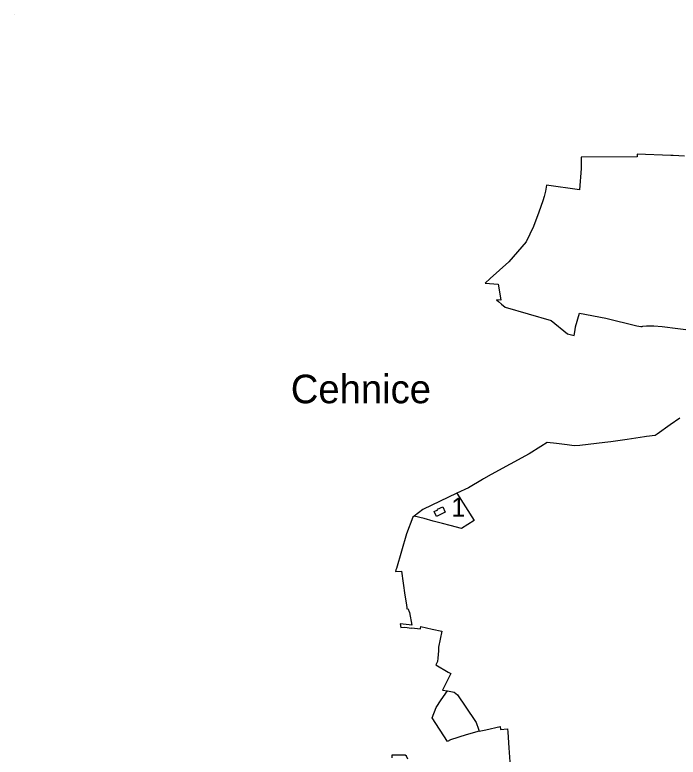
# Model space of a CAD drawing. Extents: x -783999 to -781353, y -1138035 to -1135203.
# Drawn here: x -783999 to -782885, y -1136634 to -1135387 of the extents above; entities that cross this region are included whole.
import ezdxf

# ---------------------------------------------------------------- set-up
doc = ezdxf.new("R2010")
doc.units = 0
for name, color, linetype in [('KU_OST', 7, 'Continuous'), ('LES_ZV', 7, 'Continuous'), ('Level 255', 7, 'Continuous'), ('NERES_HRA', 7, 'Continuous'), ('NERES_SET', 7, 'Continuous'), ('OVNE_PRE', 7, 'Continuous'), ('OVNI_SET', 7, 'Continuous')]:
    doc.layers.add(name, color=color, linetype=linetype)

msp = doc.modelspace()

# ---------------------------------------------------------------- linework, layer by layer
at = {"layer": 'LES_ZV'}
msp.add_lwpolyline([(-783220, -1136587.1), (-783219.2, -1136590.7), (-783241, -1136596.4), (-783267.4, -1136605.1), (-783272.2, -1136608), (-783297.9, -1136567.9), (-783291.4, -1136550.8), (-783282.6, -1136537.8), (-783272, -1136522.7)], dxfattribs=at)
at = {"layer": 'NERES_HRA'}
msp.add_lwpolyline([(-783294.3, -1136221.4), (-783288.3, -1136218.6), (-783288.7, -1136217.7), (-783280.2, -1136213.7), (-783275.9, -1136222.8), (-783290.5, -1136229.6), (-783294.3, -1136221.4)], dxfattribs=at)
at = {"layer": 'NERES_SET'}
msp.add_lwpolyline([(-783256.4, -1136190.8), (-783227.4, -1136236.5), (-783248.9, -1136250.2), (-783267.9, -1136245), (-783280.8, -1136241.5), (-783296, -1136237.4), (-783311.2, -1136233.2), (-783328, -1136229.2)], dxfattribs=at)
at = {"layer": 'OVNE_PRE'}
msp.add_line((-783998.9, -1135387.1), (-783998.9, -1135387.1), dxfattribs=at)
for points in [[(-782874.2, -1135624.5), (-782892.9, -1135623.6), (-782897.2, -1135623.4), (-782953.5, -1135620.9), (-782953.7, -1135625.5), (-783047.5, -1135626.2), (-783047.6, -1135645.2), (-783050.3, -1135680.9), (-783106.1, -1135673.1), (-783107.5, -1135683.3), (-783109.7, -1135692.3), (-783112.3, -1135699.7), (-783119, -1135718.4), (-783127.9, -1135742.9), (-783140.2, -1135768.7), (-783169.1, -1135801.8), (-783200.3, -1135830.3), (-783208.9, -1135838), (-783186.9, -1135839.7), (-783186.5, -1135842.2), (-783182.7, -1135866.6), (-783190, -1135865.9), (-783186.5, -1135868.9), (-783181.3, -1135873.3), (-783175.2, -1135878.4), (-783098.2, -1135900.8), (-783070.7, -1135923), (-783059.4, -1135925.7), (-783058, -1135916), (-783057.3, -1135911), (-783050.3, -1135888.2), (-783006.5, -1135896.5), (-782954, -1135909.4), (-782947.4, -1135910.7), (-782945.3, -1135910.4), (-782943.8, -1135910.2), (-782937.8, -1135909.3), (-782933, -1135909.4), (-782925.7, -1135909.8), (-782911.6, -1135910.4), (-782885.1, -1135913.8), (-782819.5, -1135922.3)], [(-782882, -1136064.9), (-782898.1, -1136076.1), (-782920, -1136091.3), (-782923.3, -1136093.5), (-782938, -1136095.7), (-782941.1, -1136096.1), (-782970.6, -1136100.4), (-782998.1, -1136104.3), (-783008, -1136105.7), (-783050, -1136110.5), (-783059.4, -1136111), (-783071.4, -1136109.6), (-783089.1, -1136107.4), (-783104.7, -1136105.5), (-783115.6, -1136112.3), (-783135, -1136124.4), (-783198.9, -1136159.1), (-783211.5, -1136166.6), (-783213.6, -1136167.8), (-783236.7, -1136181.5), (-783256.4, -1136190.8), (-783313.7, -1136217.9), (-783328, -1136229.2), (-783330.6, -1136231.2), (-783341.1, -1136259.2), (-783358, -1136317), (-783358.7, -1136319.3), (-783359.5, -1136322)]]:
    msp.add_lwpolyline(points, dxfattribs=at)
at = {"layer": 'OVNI_SET'}
for points in [[(-783359.5, -1136322), (-783349.2, -1136321.8), (-783343.6, -1136361.8), (-783341.3, -1136378), (-783340.5, -1136383.1), (-783340.3, -1136384.7), (-783339, -1136384.5), (-783335.9, -1136391), (-783332.2, -1136412.5), (-783336.6, -1136412), (-783351.4, -1136410.1), (-783350.8, -1136416.1), (-783343.8, -1136415.6), (-783343.8, -1136415.9), (-783332.9, -1136417.2), (-783332.9, -1136417), (-783317.4, -1136418.8), (-783316.9, -1136414.5), (-783297.8, -1136418.9), (-783281.7, -1136422.6), (-783287.4, -1136449.1), (-783287.4, -1136455.5), (-783288.5, -1136467.8), (-783289, -1136473.4), (-783291.6, -1136479), (-783270.8, -1136491.1), (-783266.5, -1136493.4), (-783279.4, -1136519.6), (-783280.3, -1136521.5), (-783272, -1136522.7), (-783261.2, -1136524.9), (-783255.6, -1136529.2), (-783226.2, -1136572.4), (-783224.2, -1136575.7), (-783220, -1136587.1), (-783219.2, -1136590.7), (-783207.7, -1136588), (-783183.5, -1136582.5), (-783183.1, -1136587.8)], [(-783183.1, -1136587.8), (-783171.2, -1136586.6), (-783170.8, -1136592.3), (-783168.9, -1136618.6), (-783167.3, -1136642.1)], [(-783339, -1136637.7), (-783341.2, -1136632.6), (-783343.3, -1136630.5), (-783365.8, -1136630.7), (-783365.8, -1136635.1)]]:
    msp.add_lwpolyline(points, dxfattribs=at)

# ---------------------------------------------------------------- texts
at = {"layer": 'KU_OST'}
msp.add_text('Cehnice', height=48, dxfattribs=at).set_placement((-783535.4, -1136039.6))
at = {"layer": 'Level 255'}
msp.add_text('1', height=32, dxfattribs=at).set_placement((-783265.9, -1136230.3))

doc.saveas('drawing.dxf')
